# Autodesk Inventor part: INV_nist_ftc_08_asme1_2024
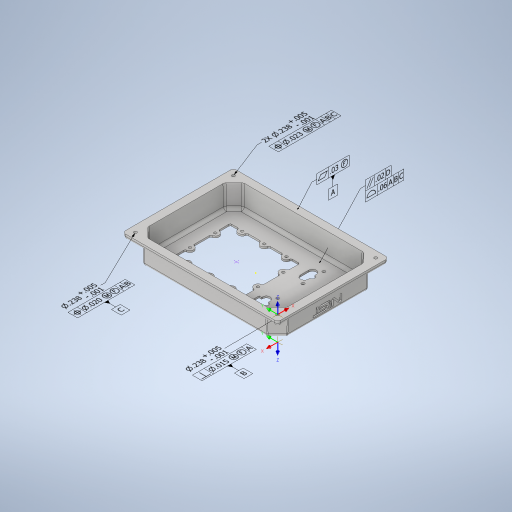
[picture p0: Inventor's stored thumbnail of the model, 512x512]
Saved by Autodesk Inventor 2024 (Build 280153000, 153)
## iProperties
Created: 2016-11
Part Number: INV_nist_ftc_08_asme1_2024
Material: Generic
Document SubType Name: Modeling
Designer: t_liuje
Density: 1 g/cm^3
Appearance: Default
Author: t_liuje
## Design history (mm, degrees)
node "Blocks"
  sketch "Block1"
    geometry: L1 (17.204, 76.896)-(6.4, 76.896); L2 (18.296, 92.7)-(18.296, 77.988); L3 (15.48, 83.59)-(15.48, 92.642); L4 (6.4, 108.85)-(6.4, 83.246); L5 (9.561, 108.85)-(6.4, 108.85); L6 (9.561, 102.44)-(9.561, 108.85); L7 (21.4, 102.44)-(9.561, 102.44); L8 (21.4, 99.338)-(21.4, 102.44); L9 (9.561, 99.338)-(21.4, 99.338); L10 (9.561, 83.648)-(9.561, 99.338); L11 (12.377, 93.16)-(12.377, 83.533); L12 (21.4, 77.959)-(21.4, 93.16); L13 (6.4, 73.763)-(17.204, 73.763); L14 (6.4, 76.896)-(6.4, 73.763); L15 (18.124, 67.902)-(7.023, 57.637); L16 (6.4, 68.62)-(17.808, 68.62); L17 (6.4, 71.752)-(6.4, 68.62); L18 (17.882, 71.752)-(6.4, 71.752); L19 (9.79, 56.022)-(20.08, 65.489); L20 (21.4, 55.085)-(10.156, 55.085); L21 (21.4, 51.982)-(21.4, 55.085); L22 (9.237, 51.982)-(21.4, 51.982); A1 r 1.093 centre (17.204, 77.988) between (17.204, 76.896) and (18.296, 77.988); A2 r 1.417 centre (16.891, 92.519) between (18.296, 92.7) and (15.48, 92.642); A3 r 4.547 centre (10.946, 83.246) between (6.4, 83.246) and (15.48, 83.59); A4 r 1.41 centre (10.966, 83.533) between (9.561, 83.648) and (12.377, 83.533); A5 r 4.568 centre (16.888, 92.441) between (21.4, 93.16) and (12.377, 93.16); A6 r 4.196 centre (17.204, 77.959) between (17.204, 73.763) and (21.4, 77.959); A7 r 3.261 centre (9.237, 55.243) between (7.023, 57.637) and (9.237, 51.982); A8 r 0.415 centre (17.842, 68.207) between (18.124, 67.902) and (17.808, 68.62); A9 r 3.517 centre (17.882, 68.235) between (20.08, 65.489) and (17.882, 71.752); A10 r 0.54 centre (10.156, 55.625) between (9.79, 56.022) and (10.156, 55.085); 1 further point
    constraints: 44 end point, 20 point on circle, 10 centre point
sketch "Sketch1"
  geometry: L1 (155.804, -111.354)-(-155.804, -111.354); L2 (-155.804, -111.354)-(-155.804, 111.354); L3 (-155.804, 111.354)-(155.804, 111.354); L4 (155.804, 111.354)-(155.804, -111.354); L5 (0, -145.063)-(0, 157.515); L6 (136.916, 0)-(-164.263, 0); 1 further point
  constraints: 12 end point, 2 horizontal, 2 parallel, 2 point on line, 1 perpendicular, 1 vertical, 2 other
  dimensions: "d0" = 311.6072 distance of L2.end L3.end; "d1" = 222.7072 distance of L1.end L2.end
extrude "Extrusion1" new body sketch "Sketch1" distance "d2" = 10.16; taper "d3" = 0 deg
feature "FaceDraft1" dims angle "d4" = -2.5 deg
sketch "Sketch2"
  geometry: L1 (0, -151.447)-(0, 170.59); L2 (373.907, 0)-(-297.418, 0); L3 (-122.72, -102.019)-(122.72, -102.019); L4 (145.58, -79.159)-(145.58, 79.159); L5 (122.72, 102.019)-(-122.72, 102.019); L6 (-145.58, 79.159)-(-145.58, -79.159); L7 (-122.72, 102.019)-(-145.58, 79.159); L8 (-145.58, -79.159)-(-122.72, -102.019); L9 (122.72, -102.019)-(145.58, -79.159); L10 (145.58, 79.159)-(122.72, 102.019); 5 further points
  constraints: 20 end point, 10 point on line, 2 horizontal, 2 parallel, 1 perpendicular, 1 vertical, 2 other
  dimensions: "d5" = 291.1602 distance of point (145.58, 102.019) point (-145.58, 102.019); "d6" = 204.0382 distance of point (145.58, -102.019) point (145.58, 102.019); "d141" = 22.86 distance of L5.end point (-145.58, 102.019); "d142" = 22.86 distance of L6.start point (-145.58, 102.019) (derived); "d143" = 22.86 distance of L6.end point (-145.58, -102.019) (derived); "d144" = 22.86 distance of L3.start point (-145.58, -102.019) (derived); "d145" = 22.86 distance of L3.end point (145.58, -102.019) (derived); "d146" = 22.86 distance of L4.start point (145.58, -102.019) (derived); "d147" = 22.86 distance of L4.end point (145.58, 102.019) (derived); "d148" = 22.86 distance of L5.start point (145.58, 102.019) (derived)
extrude "Extrusion2" join sketch "Sketch2" distance "d7" = 38.1; taper "d8" = 0 deg
feature "FaceDraft2" dims angle "d9" = 2.5 deg
workplane "Work Plane1"
sketch "Sketch3"
  geometry: L1 (0, -206.645)-(0, 206.645); L2 (-285.873, 0)-(333.246, 0); L3 (-119.456, -94.158)-(119.456, -94.158); L4 (137.719, -75.895)-(137.719, 75.895); L5 (119.456, 94.158)-(-119.456, 94.158); L6 (-137.719, 75.895)-(-137.719, -75.895); L7 (-119.456, -94.158)-(-137.719, -75.895); L8 (-137.719, 75.895)-(-119.456, 94.158); L9 (119.456, 94.158)-(137.719, 75.895); L10 (119.456, -94.158)-(137.719, -75.895); 6 further points
  constraints: 20 end point, 9 point on line, 2 parallel, 2 perpendicular, 1 coincident, 1 horizontal, 1 midpoint, 1 vertical, 2 other
  dimensions: "d11" = 275.4376 distance of point (-137.719, 94.158) point (137.719, 94.158); "d12" = 188.3156 distance of point (137.719, 94.158) point (137.719, -94.158); "d16" = 18.2626 distance of L3.start point (-137.719, -94.158); "d17" = 18.2626 distance of L6.end point (-137.719, -94.158) (= d16); "d18" = 18.2626 distance of L6.start point (-137.719, 94.158) (= d16); "d19" = 18.2626 distance of L5.end point (-137.719, 94.158) (= d18); "d20" = 18.2626 distance of L5.start point (137.719, 94.158) (= d16); "d21" = 18.2626 distance of L4.end point (137.719, 94.158) (= d20); "d22" = 18.2626 distance of L3.end point (137.719, -94.158) (= d16); "d23" = 18.2626 distance of L4.start point (137.719, -94.158) (= d22)
extrude "Extrusion3" cut sketch "Sketch3" stored distance "d13" = 38.1; taper "d14" = 0 deg
feature "FaceDraft3" dims angle "d15" = 2.5 deg
fillet "Fillet1" dims "d24" = 3.048
fillet "Fillet2" dims "d25" = 6.096
sketch "Sketch4"
  geometry: L1 (-127.635, 79.375)-(-121.285, 79.375); L2 (-118.11, 76.2)-(-118.11, -76.2); L3 (-121.285, -79.375)-(-127.635, -79.375); L4 (-130.81, -76.2)-(-130.81, 76.2); L5 (-237.716, 0)-(182.507, 0); L6 (-155.804, -105.263)-(-155.804, 105.263) reference; A1 r 3.175 centre (-127.635, 76.2) between (-127.635, 79.375) and (-130.81, 76.2); A2 r 3.175 centre (-121.285, 76.2) between (-118.11, 76.2) and (-121.285, 79.375); A3 r 3.175 centre (-127.635, -76.2) between (-130.81, -76.2) and (-127.635, -79.375); A4 r 3.175 centre (-121.285, -76.2) between (-121.285, -79.375) and (-118.11, -76.2); 4 further points
  constraints: 10 end point, 8 point on circle, 8 tangent, 7 point on line, 4 centre point, 3 equal radius, 2 horizontal, 2 parallel, 1 perpendicular, 1 other
  dimensions: "d26" = 12.7 distance of point (-118.11, -79.375) point (-130.81, -79.375); "d27" = 158.75 distance of point (-118.11, 79.375) point (-118.11, -79.375); "d28" = 24.9936 distance between parallel lines of L6 L4; "d29" = 3.175 radius of A1
extrude "Extrusion4" cut sketch "Sketch4" distance "d30" = 1.27; taper "d31" = 0 deg
fillet "Fillet3" dims "d32" = 0.762
sketch "Sketch5"
  geometry: L1 (-252.407, 0)-(214.454, 0); L2 (0, 149.282)-(0, -167.26); L3 (-155.804, -105.263)-(-155.804, 105.263) reference; L4 (-90.016, -57.15)-(-107.95, -57.15); L5 (-45.566, -57.15)-(-75.084, -57.15); L6 (31.75, -57.15)-(13.816, -57.15); L7 (0, -57.15)-(-30.634, -57.15); L8 (31.75, -32.866)-(31.75, -57.15); L9 (31.75, 57.15)-(31.75, 32.866); L10 (31.75, 17.934)-(31.75, -17.934); L11 (13.816, 57.15)-(31.75, 57.15); L12 (-30.634, 57.15)-(0, 57.15); L13 (-107.95, 57.15)-(-90.016, 57.15); L14 (-75.084, 57.15)-(-45.566, 57.15); L15 (-107.95, 32.866)-(-107.95, 57.15); L16 (-107.95, -57.15)-(-107.95, -32.866); L17 (-107.95, -17.934)-(-107.95, 17.934); L18 (155.804, 105.263)-(155.804, -105.263) reference; L19 (-149.713, 111.354)-(149.713, 111.354) reference; L20 (46.99, 52.705)-(52.07, 52.705); L21 (52.07, 40.005)-(46.99, 40.005); L22 (46.99, 40.005)-(46.99, 52.705); L23 (52.07, 38.1)-(52.07, 40.005); L24 (52.07, 52.705)-(52.07, 54.61); L25 (67.31, 54.61)-(67.31, 51.435); L26 (67.31, 41.275)-(67.31, 38.1); L27 (96.85, -35.56)-(121.59, -35.56); L28 (123.19, -37.16)-(123.19, -61.9); L29 (121.59, -63.5)-(96.85, -63.5); L30 (95.25, -61.9)-(95.25, -37.16); L31 (149.713, -111.354)-(-149.713, -111.354) reference; L32 (67.31, -38.1)-(67.31, -41.275); L33 (67.31, -51.435)-(67.31, -54.61); L34 (52.07, -38.1)-(52.07, -54.61); C1 r 2.705 at (-82.55, 55.626); C2 r 2.705 at (-38.1, 55.626); C3 r 2.705 at (6.35, 55.626); C4 r 2.705 at (-82.55, -55.626); C5 r 2.705 at (-38.1, -55.626); C6 r 2.705 at (6.35, -55.626); C7 r 2.705 at (-106.426, 25.4); C8 r 2.705 at (-106.426, -25.4); C9 r 2.705 at (30.226, 25.4); C10 r 2.705 at (30.226, -25.4); C11 r 3.073 at (69.85, 67.31); C12 r 2.896 at (69.85, 25.4); C13 r 3.175 at (109.22, -20.955); C14 r 3.175 at (109.22, -78.105); C15 r 2.896 at (69.85, -67.31); C16 r 3.073 at (69.85, -25.4); A1 r 7.62 centre (-82.55, 55.626) between (-90.016, 57.15) and (-75.084, 57.15); A2 r 7.62 centre (-38.1, 55.626) between (-45.566, 57.15) and (-30.634, 57.15); A3 r 7.62 centre (6.35, 55.626) between (-1.116, 57.15) and (13.816, 57.15); A4 r 7.62 centre (-82.55, -55.626) between (-75.084, -57.15) and (-90.016, -57.15); A5 r 7.62 centre (-38.1, -55.626) between (-30.634, -57.15) and (-45.566, -57.15); A6 r 7.62 centre (6.35, -55.626) between (13.816, -57.15) and (-1.116, -57.15); A7 r 7.62 centre (-106.426, 25.4) between (-107.95, 17.934) and (-107.95, 32.866); A8 r 7.62 centre (-106.426, -25.4) between (-107.95, -32.866) and (-107.95, -17.934); A9 r 7.62 centre (30.226, 25.4) between (31.75, 32.866) and (31.75, 17.934); A10 r 7.62 centre (30.226, -25.4) between (31.75, -17.934) and (31.75, -32.866); A11 r 15.291 centre (111.76, 63.5) between (96.787, 60.397) and (96.787, 66.603); A12 r 3.175 centre (97.46, 63.5) between (96.787, 66.603) and (96.787, 60.397); A13 r 5.08 centre (67.31, 46.355) between (67.31, 41.275) and (67.31, 51.435); A14 r 7.62 centre (59.69, 54.61) between (67.31, 54.61) and (52.07, 54.61); A15 r 7.62 centre (59.69, 38.1) between (52.07, 38.1) and (67.31, 38.1); A16 r 1.6 centre (96.85, -37.16) between (96.85, -35.56) and (95.25, -37.16); A17 r 1.6 centre (121.59, -37.16) between (123.19, -37.16) and (121.59, -35.56); A18 r 1.6 centre (96.85, -61.9) between (95.25, -61.9) and (96.85, -63.5); A19 r 1.6 centre (121.59, -61.9) between (121.59, -63.5) and (123.19, -61.9); A20 r 7.62 centre (59.69, -54.61) between (52.07, -54.61) and (67.31, -54.61); A21 r 7.62 centre (59.69, -38.1) between (67.31, -38.1) and (52.07, -38.1); A22 r 5.08 centre (67.31, -46.355) between (67.31, -51.435) and (67.31, -41.275); 4 further points
  constraints: 60 end point, 44 point on circle, 38 centre point, 32 parallel, 16 point on line, 16 tangent, 13 perpendicular, 10 coincident, 10 collinear, 7 horizontal, 4 equal radius, 4 vertical, 2 symmetric about line, 1 other
  dimensions: "d33" = 139.7 distance of L6.start L4.end; "d34" = 114.3 distance of L9.start L6.start; "d36" = 5.4102 diameter of C1; "d39" = 15.24 diameter of A1; "d40" = 5.4102 diameter of C2; "d41" = 15.24 diameter of A2; "d42" = 5.4102 diameter of C3; "d43" = 15.24 diameter of A3; "d48" = 44.45 distance of A2.centre A1.centre; "d49" = 44.45 distance of A2.centre A3.centre; "d50" = 5.4102 diameter of C4; "d51" = 15.24 diameter of A4; "d52" = 5.4102 diameter of C5; "d53" = 15.24 diameter of A5; "d54" = 5.4102 diameter of C6; "d55" = 15.24 diameter of A6; "d56" = 44.45 distance of A5.centre A4.centre; "d57" = 44.45 distance of A5.centre A6.centre; "d62" = 44.45 distance of C4.centre C5.centre (derived); "d63" = 44.45 distance of C6.centre C5.centre (derived); "d64" = 5.4102 diameter of C7; "d65" = 15.24 diameter of A7; "d66" = 5.4102 diameter of C8; "d67" = 15.24 diameter of A8; "d68" = 50.8 distance of A8.centre C7.centre; "d70" = 5.4102 diameter of C9; "d71" = 15.24 diameter of A9; "d72" = 5.4102 diameter of C10; "d73" = 15.24 diameter of A10; "d74" = 50.8 distance of A10.centre C9.centre; "d76" = 114.3 distance between parallel lines of L5 L14; "d77" = 139.7 distance between parallel lines of L10 L17; "d78" = 47.8536 distance between parallel lines of L3 L17; "d79" = 1.524 distance from line of L14 C1.centre; "d80" = 25.4 distance from line of L15 C1.centre; "d81" = 1.524 distance from line of L12 A2.centre; "d82" = 1.524 distance from line of L12 A3.centre; "d83" = 1.524 distance from line of L5 C4.centre; "d84" = 1.524 distance from line of A5.centre L5; "d85" = 25.4 distance from line of L16 A4.centre; "d86" = 1.524 distance from line of L6 A6.centre; "d87" = 1.524 distance from line of L8 A10.centre; "d88" = 1.524 distance from line of L16 C8.centre; "d89" = 30.5816 diameter of A11; "d90" = 44.0436 distance from line of L18 A11.centre; "d91" = 47.8536 distance from line of A11.centre L19; "d92" = 14.3002 distance of A12.centre A11.centre; "d93" = 47.8536 distance from line of A12.centre L19 (= d91); "d94" = 6.35 diameter of A12; "d95" = 10.16 diameter of A13; "d96" = 5.08 distance between parallel lines of L24 L22; "d97" = 5.08 distance of L21.start L21.end (= d96); "d98" = 12.7 distance of L21.end L20.start; "d99" = 15.24 distance between parallel lines of L24 L25; "d100" = 6.35 distance from line of A13.centre L20; "d101" = 56.7436 distance from line of L19 A14.centre; "d102" = 96.1136 distance from line of L18 A14.centre; "d103" = 16.51 distance of A15.centre A14.centre; "d104" = 1.905 distance from line of A14.centre L20; "d105" = 6.1468 diameter of C11; "d106" = 10.16 horizontal distance of C11.centre A14.centre; "d107" = 12.7 vertical distance of A14.centre C11.centre; "d108" = 10.16 horizontal distance of A15.centre C12.centre (derived); "d109" = 12.7 vertical distance of A15.centre C12.centre (derived)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
extrude "Extrusion5" cut sketch "Sketch5" stored distance "d130" = 25.4; taper "d131" = 0 deg
sketch "Sketch8" dims "d6" = 204.0382
  geometry: L1 (149.713, 111.354)-(-149.713, 111.354) reference; L2 (-155.804, 105.263)-(-155.804, -105.263) reference; C1 r 3.023 at (-142.875, 98.425); 1 further point
  constraints: 1 centre point, 1 coincident
  dimensions: "d132" = 12.9286 distance from line of L1 point (-142.875, 98.425); "d133" = 12.9286 distance from line of L2 point (-142.875, 98.425); "d876" = 6.0452 diameter of C1
extrude "Extrusion7" cut sketch "Sketch8" stored distance "d877" = 25.4; taper "d878" = 0 deg
mirror "Mirror1"
mirror "Mirror2"
sketch "Sketch6"
  geometry: L1 (183.284, 13.514)-(183.095, 9.18) reference; L2 (183.095, 9.18)-(189.186, 8.914) reference; L3 (189.186, 8.914)-(189.375, 13.248) reference; L4 (-27.242, 13.514)-(183.284, 13.514) reference; 2 further points; 1 other entity
  constraints: 1 other
  dimensions: "d150" = 83.4136 dimension on L3.end; "d151" = 25.4 dimension on L4
extrude "Extrusion6" cut sketch "Sketch6" distance "d152" = 2.54; taper "d153" = 0 deg
fillet "Fillet4" dims "d196" = 3.175
sketch "Sketch10" dims "d6" = 204.0382
  geometry: C1 r 3.023 at (142.875, -98.425) reference; 3 further points
  constraints: 1 coincident
sketch "Sketch11" dims "d6" = 204.0382
  geometry: C1 r 3.023 at (142.875, 98.425) reference; 2 further points
  constraints: 1 coincident
sketch "Sketch12" dims "d6" = 204.0382
  geometry: 2 further points
split "Split1"
body "Solid1"
node "Annotations"
node "Tolerance Features"
sketch "Sketch7"
  geometry: L1 (70.782, -29.383)-(70.782, 0); L2 (170.85, 0)-(170.85, -29.383); L3 (170.85, -29.383)-(141.467, 0); L4 (160.074, -29.383)-(130.691, 0); L5 (149.297, -29.383)-(119.915, 0); L6 (138.521, -29.383)-(109.138, 0); L7 (127.745, -29.383)-(98.362, 0); L8 (116.969, -29.383)-(87.586, 0); L9 (106.192, -29.383)-(76.809, 0); L10 (95.416, -29.383)-(70.782, -4.749); L11 (84.64, -29.383)-(70.782, -15.525); L12 (73.863, -29.383)-(70.782, -26.301); L13 (170.85, -18.607)-(152.244, 0); L14 (170.85, -7.83)-(163.02, 0)
  constraints: 28 end point, 12 parallel, 5 point on line, 1 vertical, 24 other
node "Projected Loop1"
node "Block1:1" dims "d150" = 83.4136, "d151" = 25.4
node "Planar Surface 1" dims "d315" = 5.33671 (derived), "d316" = 3.69003 (derived), "d347" = 15.24 (derived), "d348" = 0 (derived), "d349" = 0 (derived), "d505" = 0 (derived), "d506" = 0 (derived), "d657" = 2.7782 (derived), "d658" = 3.42425 (derived), "d659" = 0.381 (derived), "d660" = 0 (derived), "d661" = 0 (derived), "d795" = 0.26791 (derived), "d796" = 4.34708 (derived), "d797" = 0.762 (derived), "d798" = 0 (derived), "d799" = 0 (derived), "d886" = 11.18939 (derived), "d887" = 0 (derived), "d888" = 3.21915 (derived), "d889" = 6.0452 (derived), "d890" = 0.508 (derived), "d891" = 0 (derived), "d892" = 0 (derived)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
node "Datum Reference Frame 1"
node "General Note 1"
node "Leader Text 5"
node "Leader Text 6"
node "General Surface Profile Tolerance"
node "Planar Surface 35"
node "Feature Control Frame 53"
node "Leader Text 16"
node "Feature Control Frame 70"
node "Datum Identifier 41" dims "d315" = 5.33671 (derived), "d316" = 3.69003 (derived), "d347" = 15.24 (derived), "d348" = 0 (derived), "d349" = 0 (derived), "d505" = 0 (derived), "d506" = 0 (derived), "d657" = 2.7782 (derived), "d658" = 3.42425 (derived), "d659" = 0.381 (derived), "d660" = 0 (derived), "d661" = 0 (derived), "d795" = 0.26791 (derived), "d796" = 4.34708 (derived), "d797" = 0.762 (derived), "d798" = 0 (derived), "d799" = 0 (derived), "d886" = 11.18939 (derived), "d887" = 0 (derived), "d888" = 3.21915 (derived), "d889" = 6.0452 (derived), "d890" = 0.508 (derived), "d891" = 0 (derived), "d892" = 0 (derived)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
node "Simple Hole 35" dims "d315" = 5.33671 (derived), "d316" = 3.69003 (derived), "d347" = 15.24 (derived), "d348" = 0 (derived), "d349" = 0 (derived), "d505" = 0 (derived), "d506" = 0 (derived), "d657" = 2.7782 (derived), "d658" = 3.42425 (derived), "d659" = 0.381 (derived), "d660" = 0 (derived), "d661" = 0 (derived), "d795" = 0.26791 (derived), "d796" = 4.34708 (derived), "d797" = 0.762 (derived), "d798" = 0 (derived), "d799" = 0 (derived), "d886" = 11.18939 (derived), "d887" = 0 (derived), "d888" = 3.21915 (derived), "d889" = 6.0452 (derived), "d890" = 0.508 (derived), "d891" = 0 (derived), "d892" = 0 (derived)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
node "Datum Reference Frame 20"
node "Datum Reference Frame 21"
node "Simple Hole 36" dims "d315" = 5.33671 (derived), "d316" = 3.69003 (derived), "d347" = 15.24 (derived), "d348" = 0 (derived), "d349" = 0 (derived), "d505" = 0 (derived), "d506" = 0 (derived), "d657" = 2.7782 (derived), "d658" = 3.42425 (derived), "d659" = 0.381 (derived), "d660" = 0 (derived), "d661" = 0 (derived), "d795" = 0.26791 (derived), "d796" = 4.34708 (derived), "d797" = 0.762 (derived), "d798" = 0 (derived), "d799" = 0 (derived), "d886" = 11.18939 (derived), "d887" = 0 (derived), "d888" = 3.21915 (derived), "d889" = 6.0452 (derived), "d890" = 0.508 (derived), "d891" = 0 (derived), "d892" = 0 (derived)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
node "Diameter Dimension 30" dims "d5" = 291.1602, "d6" = 204.0382, "d141" = 22.86, "d142" = 22.86 (derived), "d143" = 22.86 (derived), "d144" = 22.86 (derived), "d145" = 22.86 (derived), "d146" = 22.86 (derived), "d147" = 22.86 (derived), "d148" = 22.86 (derived), "d889" = 6.0452 (derived)
node "Feature Control Frame 76"
node "Datum Identifier 45" dims "d315" = 5.33671 (derived), "d316" = 3.69003 (derived), "d347" = 15.24 (derived), "d348" = 0 (derived), "d349" = 0 (derived), "d505" = 0 (derived), "d506" = 0 (derived), "d657" = 2.7782 (derived), "d658" = 3.42425 (derived), "d659" = 0.381 (derived), "d660" = 0 (derived), "d661" = 0 (derived), "d795" = 0.26791 (derived), "d796" = 4.34708 (derived), "d797" = 0.762 (derived), "d798" = 0 (derived), "d799" = 0 (derived), "d886" = 11.18939 (derived), "d887" = 0 (derived), "d888" = 3.21915 (derived), "d889" = 6.0452 (derived), "d890" = 0.508 (derived), "d891" = 0 (derived), "d892" = 0 (derived)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
node "Datum Reference Frame 22"
node "Diameter Dimension 29" dims "d5" = 291.1602, "d6" = 204.0382, "d141" = 22.86, "d142" = 22.86 (derived), "d143" = 22.86 (derived), "d144" = 22.86 (derived), "d145" = 22.86 (derived), "d146" = 22.86 (derived), "d147" = 22.86 (derived), "d148" = 22.86 (derived), "d896" = 6.0452 (derived)
node "Feature Control Frame 77"
node "Datum Identifier 46" dims "d315" = 5.33671 (derived), "d316" = 3.69003 (derived), "d347" = 15.24 (derived), "d348" = 0 (derived), "d349" = 0 (derived), "d505" = 0 (derived), "d506" = 0 (derived), "d657" = 2.7782 (derived), "d658" = 3.42425 (derived), "d659" = 0.381 (derived), "d660" = 0 (derived), "d661" = 0 (derived), "d795" = 0.26791 (derived), "d796" = 4.34708 (derived), "d797" = 0.762 (derived), "d798" = 0 (derived), "d799" = 0 (derived), "d886" = 11.18939 (derived), "d887" = 0 (derived), "d888" = 3.21915 (derived), "d889" = 6.0452 (derived), "d890" = 0.508 (derived), "d891" = 0 (derived), "d892" = 0 (derived)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
node "Datum Reference Frame 23"
node "Parallel Axes Pattern 4"
node "Simple Hole 37"
node "Simple Hole 38"
node "Diameter Dimension 32" dims "d5" = 291.1602, "d6" = 204.0382, "d141" = 22.86, "d142" = 22.86 (derived), "d143" = 22.86 (derived), "d144" = 22.86 (derived), "d145" = 22.86 (derived), "d146" = 22.86 (derived), "d147" = 22.86 (derived), "d148" = 22.86 (derived), "d910" = 6.0452 (derived)
node "Feature Control Frame 78"
node "Planar Surface 66" dims "d315" = 5.33671 (derived), "d316" = 3.69003 (derived), "d347" = 15.24 (derived), "d348" = 0 (derived), "d349" = 0 (derived), "d505" = 0 (derived), "d506" = 0 (derived), "d657" = 2.7782 (derived), "d658" = 3.42425 (derived), "d659" = 0.381 (derived), "d660" = 0 (derived), "d661" = 0 (derived), "d795" = 0.26791 (derived), "d796" = 4.34708 (derived), "d797" = 0.762 (derived), "d798" = 0 (derived), "d799" = 0 (derived), "d886" = 11.18939 (derived), "d887" = 0 (derived), "d888" = 3.21915 (derived), "d889" = 6.0452 (derived), "d890" = 0.508 (derived), "d891" = 0 (derived), "d892" = 0 (derived)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
node "Feature Control Frame 80"
node "Datum Identifier 47" dims "d315" = 5.33671 (derived), "d316" = 3.69003 (derived), "d347" = 15.24 (derived), "d348" = 0 (derived), "d349" = 0 (derived), "d505" = 0 (derived), "d506" = 0 (derived), "d657" = 2.7782 (derived), "d658" = 3.42425 (derived), "d659" = 0.381 (derived), "d660" = 0 (derived), "d661" = 0 (derived), "d795" = 0.26791 (derived), "d796" = 4.34708 (derived), "d797" = 0.762 (derived), "d798" = 0 (derived), "d799" = 0 (derived), "d886" = 11.18939 (derived), "d887" = 0 (derived), "d888" = 3.21915 (derived), "d889" = 6.0452 (derived), "d890" = 0.508 (derived), "d891" = 0 (derived), "d892" = 0 (derived)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
node "Datum Reference Frame 24"
node "Datum Reference Frame 25"
node "Simple Hole 39"
node "Simple Hole 40"
node "Simple Hole 41"
node "Simple Hole 42"
node "Simple Hole 43"
node "Simple Hole 44"
node "Simple Hole 45"
node "Simple Hole 46"
node "Simple Hole 47"
node "Simple Hole 48"
node "Parallel Axes Pattern 5" dims "d315" = 5.33671 (derived), "d316" = 3.69003 (derived), "d347" = 15.24 (derived), "d348" = 0 (derived), "d349" = 0 (derived), "d505" = 0 (derived), "d506" = 0 (derived), "d657" = 2.7782 (derived), "d658" = 3.42425 (derived), "d659" = 0.381 (derived), "d660" = 0 (derived), "d661" = 0 (derived), "d795" = 0.26791 (derived), "d796" = 4.34708 (derived), "d797" = 0.762 (derived), "d798" = 0 (derived), "d799" = 0 (derived), "d886" = 11.18939 (derived), "d887" = 0 (derived), "d888" = 3.21915 (derived), "d889" = 6.0452 (derived), "d890" = 0.508 (derived), "d891" = 0 (derived), "d892" = 0 (derived)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
node "Diameter Dimension 33" dims "d5" = 291.1602, "d6" = 204.0382, "d141" = 22.86, "d142" = 22.86 (derived), "d143" = 22.86 (derived), "d144" = 22.86 (derived), "d145" = 22.86 (derived), "d146" = 22.86 (derived), "d147" = 22.86 (derived), "d148" = 22.86 (derived), "d977" = 5.4102 (derived)
node "Feature Control Frame 81"
node "Datum Identifier 48" dims "d315" = 5.33671 (derived), "d316" = 3.69003 (derived), "d347" = 15.24 (derived), "d348" = 0 (derived), "d349" = 0 (derived), "d505" = 0 (derived), "d506" = 0 (derived), "d657" = 2.7782 (derived), "d658" = 3.42425 (derived), "d659" = 0.381 (derived), "d660" = 0 (derived), "d661" = 0 (derived), "d795" = 0.26791 (derived), "d796" = 4.34708 (derived), "d797" = 0.762 (derived), "d798" = 0 (derived), "d799" = 0 (derived), "d886" = 11.18939 (derived), "d887" = 0 (derived), "d888" = 3.21915 (derived), "d889" = 6.0452 (derived), "d890" = 0.508 (derived), "d891" = 0 (derived), "d892" = 0 (derived)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
node "Datum Reference Frame 26"
node "Datum Reference Frame 27"
node "Planar Surface 67"
node "Feature Control Frame 82"
node "Planar Surface 68"
node "Feature Control Frame 83"
node "Planar Surface 69"
node "Feature Control Frame 84"
node "Planar Surface 70"
node "Feature Control Frame 85"
node "Planar Surface 71"
node "Feature Control Frame 86"
node "Simple Hole 49"
node "Simple Hole 50"
node "Parallel Axes Pattern 6" dims "d315" = 5.33671 (derived), "d316" = 3.69003 (derived), "d347" = 15.24 (derived), "d348" = 0 (derived), "d349" = 0 (derived), "d505" = 0 (derived), "d506" = 0 (derived), "d657" = 2.7782 (derived), "d658" = 3.42425 (derived), "d659" = 0.381 (derived), "d660" = 0 (derived), "d661" = 0 (derived), "d795" = 0.26791 (derived), "d796" = 4.34708 (derived), "d797" = 0.762 (derived), "d798" = 0 (derived), "d799" = 0 (derived), "d886" = 11.18939 (derived), "d887" = 0 (derived), "d888" = 3.21915 (derived), "d889" = 6.0452 (derived), "d890" = 0.508 (derived), "d891" = 0 (derived), "d892" = 0 (derived)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
node "Diameter Dimension 34" dims "d5" = 291.1602, "d6" = 204.0382, "d141" = 22.86, "d142" = 22.86 (derived), "d143" = 22.86 (derived), "d144" = 22.86 (derived), "d145" = 22.86 (derived), "d146" = 22.86 (derived), "d147" = 22.86 (derived), "d148" = 22.86 (derived), "d1042" = 6.35 (derived)
node "Feature Control Frame 87"
node "Datum Identifier 49" dims "d315" = 5.33671 (derived), "d316" = 3.69003 (derived), "d347" = 15.24 (derived), "d348" = 0 (derived), "d349" = 0 (derived), "d505" = 0 (derived), "d506" = 0 (derived), "d657" = 2.7782 (derived), "d658" = 3.42425 (derived), "d659" = 0.381 (derived), "d660" = 0 (derived), "d661" = 0 (derived), "d795" = 0.26791 (derived), "d796" = 4.34708 (derived), "d797" = 0.762 (derived), "d798" = 0 (derived), "d799" = 0 (derived), "d886" = 11.18939 (derived), "d887" = 0 (derived), "d888" = 3.21915 (derived), "d889" = 6.0452 (derived), "d890" = 0.508 (derived), "d891" = 0 (derived), "d892" = 0 (derived)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
node "Datum Reference Frame 28"
node "Datum Reference Frame 29"
node "Planar Surface 72"
node "Cylindrical Surface 24"
node "Planar Surface 73"
node "Planar Surface 74"
node "Cylindrical Surface 25"
node "Planar Surface 75"
node "Cylindrical Surface 26"
node "Cylindrical Surface 27"
node "Extruded Group 6"
node "Feature Control Frame 88"
node "Simple Hole 51"
node "Simple Hole 52"
node "Parallel Axes Pattern 7" dims "d315" = 5.33671 (derived), "d316" = 3.69003 (derived), "d347" = 15.24 (derived), "d348" = 0 (derived), "d349" = 0 (derived), "d505" = 0 (derived), "d506" = 0 (derived), "d657" = 2.7782 (derived), "d658" = 3.42425 (derived), "d659" = 0.381 (derived), "d660" = 0 (derived), "d661" = 0 (derived), "d795" = 0.26791 (derived), "d796" = 4.34708 (derived), "d797" = 0.762 (derived), "d798" = 0 (derived), "d799" = 0 (derived), "d886" = 11.18939 (derived), "d887" = 0 (derived), "d888" = 3.21915 (derived), "d889" = 6.0452 (derived), "d890" = 0.508 (derived), "d891" = 0 (derived), "d892" = 0 (derived)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
node "Diameter Dimension 35" dims "d5" = 291.1602, "d6" = 204.0382, "d141" = 22.86, "d142" = 22.86 (derived), "d143" = 22.86 (derived), "d144" = 22.86 (derived), "d145" = 22.86 (derived), "d146" = 22.86 (derived), "d147" = 22.86 (derived), "d148" = 22.86 (derived), "d1058" = 5.7912 (derived)
node "Feature Control Frame 89"
node "Datum Identifier 50" dims "d315" = 5.33671 (derived), "d316" = 3.69003 (derived), "d347" = 15.24 (derived), "d348" = 0 (derived), "d349" = 0 (derived), "d505" = 0 (derived), "d506" = 0 (derived), "d657" = 2.7782 (derived), "d658" = 3.42425 (derived), "d659" = 0.381 (derived), "d660" = 0 (derived), "d661" = 0 (derived), "d795" = 0.26791 (derived), "d796" = 4.34708 (derived), "d797" = 0.762 (derived), "d798" = 0 (derived), "d799" = 0 (derived), "d886" = 11.18939 (derived), "d887" = 0 (derived), "d888" = 3.21915 (derived), "d889" = 6.0452 (derived), "d890" = 0.508 (derived), "d891" = 0 (derived), "d892" = 0 (derived)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
node "Datum Reference Frame 30"
node "Simple Hole 53"
node "Simple Hole 54"
node "Parallel Axes Pattern 8" dims "d315" = 5.33671 (derived), "d316" = 3.69003 (derived), "d347" = 15.24 (derived), "d348" = 0 (derived), "d349" = 0 (derived), "d505" = 0 (derived), "d506" = 0 (derived), "d657" = 2.7782 (derived), "d658" = 3.42425 (derived), "d659" = 0.381 (derived), "d660" = 0 (derived), "d661" = 0 (derived), "d795" = 0.26791 (derived), "d796" = 4.34708 (derived), "d797" = 0.762 (derived), "d798" = 0 (derived), "d799" = 0 (derived), "d886" = 11.18939 (derived), "d887" = 0 (derived), "d888" = 3.21915 (derived), "d889" = 6.0452 (derived), "d890" = 0.508 (derived), "d891" = 0 (derived), "d892" = 0 (derived)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
node "Diameter Dimension 36" dims "d5" = 291.1602, "d6" = 204.0382, "d141" = 22.86, "d142" = 22.86 (derived), "d143" = 22.86 (derived), "d144" = 22.86 (derived), "d145" = 22.86 (derived), "d146" = 22.86 (derived), "d147" = 22.86 (derived), "d148" = 22.86 (derived), "d1068" = 6.1468 (derived)
node "Feature Control Frame 90"
node "Datum Identifier 51" dims "d315" = 5.33671 (derived), "d316" = 3.69003 (derived), "d347" = 15.24 (derived), "d348" = 0 (derived), "d349" = 0 (derived), "d505" = 0 (derived), "d506" = 0 (derived), "d657" = 2.7782 (derived), "d658" = 3.42425 (derived), "d659" = 0.381 (derived), "d660" = 0 (derived), "d661" = 0 (derived), "d795" = 0.26791 (derived), "d796" = 4.34708 (derived), "d797" = 0.762 (derived), "d798" = 0 (derived), "d799" = 0 (derived), "d886" = 11.18939 (derived), "d887" = 0 (derived), "d888" = 3.21915 (derived), "d889" = 6.0452 (derived), "d890" = 0.508 (derived), "d891" = 0 (derived), "d892" = 0 (derived)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
node "Datum Reference Frame 31"
node "Datum Reference Frame 32"
node "Datum Reference Frame 33"
node "Cylindrical Surface 31"
node "Planar Surface 79"
node "Planar Surface 80"
node "Cylindrical Surface 32"
node "Planar Surface 81"
node "Cylindrical Surface 33"
node "Planar Surface 82"
node "Planar Surface 83"
node "Planar Surface 84"
node "Planar Surface 85"
node "Extruded Group 8"
node "Feature Control Frame 92"
node "Cylindrical Surface 34"
node "Simple Hole 55"
node "Extruded Group 9"
node "Feature Control Frame 93"
other parameters: "d10" = -3.429, "d35" = 47.8536, "d37" = 25.4, "d38" = 1.524, "d44" = 1.524 (= d38), "d45" = 1.524 (= d38), "d58" = 1.524 (= d38), "d59" = 1.524 (= d38), "d60" = 1.524 (= d38), "d61" = 25.4 (= d37), "d69" = 1.524, "d75" = 1.524, "d372" = 0, "d373" = 0, "d374" = -57.15, "d375" = -90 deg, "d376" = 0, "d377" = -90 deg, "d383" = 15.5702, "d384" = 0, "d385" = 0, "d386" = -90 deg, "d387" = 0, "d388" = -90 deg, "d394" = 0, "d395" = 0, "d396" = 0, "d397" = -90 deg, "d398" = 0, "d399" = -90 deg, "d400" = 0, "d401" = 0, "d402" = 0, "d403" = -90 deg, "d404" = 0, "d405" = -90 deg, "d920" = 0, "d921" = 0, "d922" = 0, "d923" = 90 deg, "d924" = 0, "d925" = -90 deg, "d926" = 0, "d927" = 0, "d928" = 0, "d929" = -90 deg, "d930" = 0, "d931" = -90 deg
